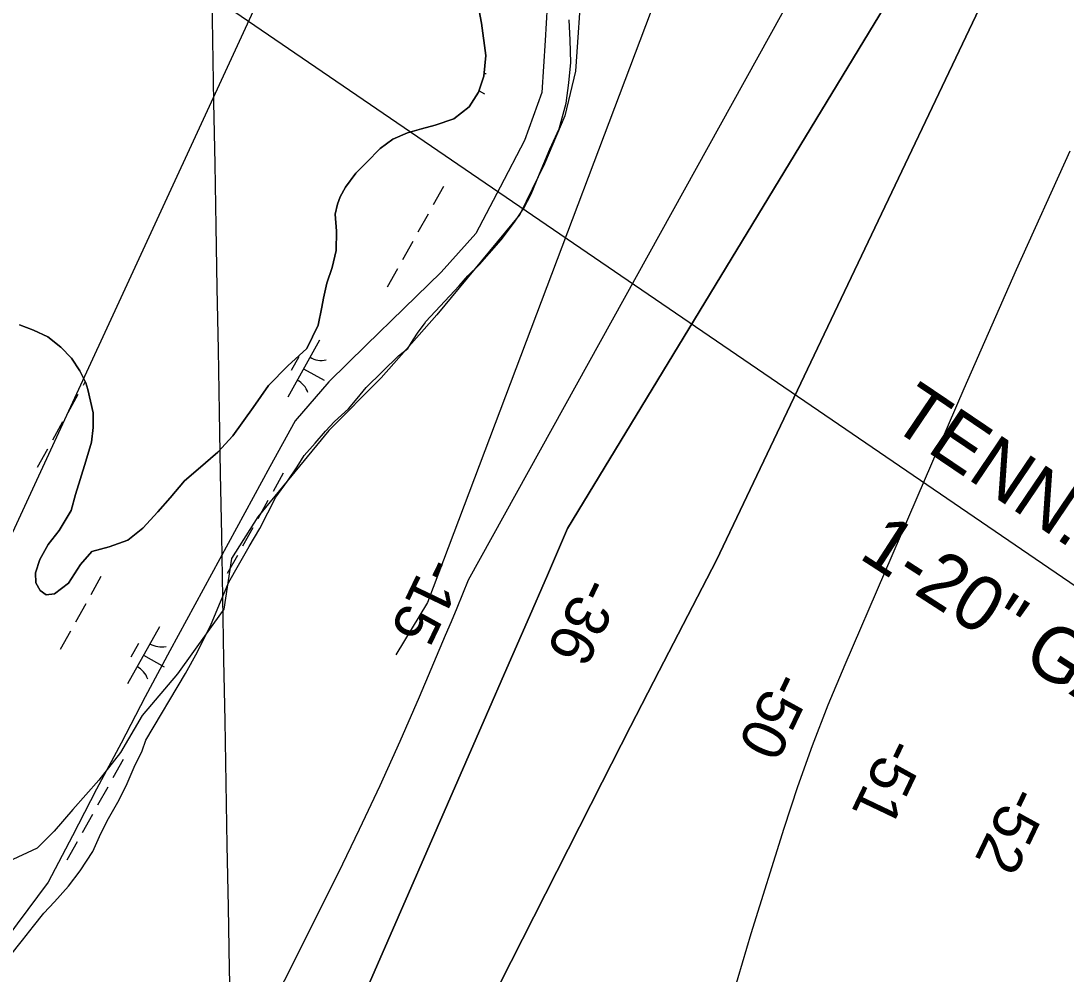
# Model space of a CAD drawing. Extents: x 3923531 to 3943530, y 207391 to 229799.
# Drawn here: x 3935451 to 3936249, y 220366 to 221095 of the extents above; entities that cross this region are included whole.
import ezdxf

# ---------------------------------------------------------------- set-up
doc = ezdxf.new("R2010")
doc.units = 0
for name, color, linetype in [('V-GRID-MAJR', 7, 'Continuous'), ('V-RIVR-EDGE', 7, 'Continuous'), ('V-RIVR-RANG', 7, 'Continuous'), ('V-RRAP-FSHR', 7, 'Continuous'), ('V-TOPO-DPTH', 7, 'Continuous'), ('V-TOPO-MAJR', 7, 'Continuous'), ('V-TOPO-MINR', 7, 'Continuous'), ('V-TOPO-SHOR', 7, 'Continuous'), ('V-UTIL-IDEN', 7, 'Continuous'), ('V-UTIL-LINE', 7, 'Continuous'), ('V-WETL-SWMP', 7, 'Continuous')]:
    doc.layers.add(name, color=color, linetype=linetype)

msp = doc.modelspace()

# ---------------------------------------------------------------- linework, layer by layer
at = {"layer": 'V-GRID-MAJR'}
msp.add_spline([(3935779.93, 210874.81), (3935760.83, 211942.59), (3935652.4, 218002.59), (3935543.98, 224062.57), (3935501.82, 226418.85)], degree=3, dxfattribs=at)
at = {"layer": 'V-RIVR-EDGE'}
msp.add_lwpolyline([(3935879.19, 221126.95), (3935874.48, 221056.23), (3935866.23, 221022.05), (3935850.9, 220985.51), (3935832.04, 220946.61), (3935768.39, 220869.99), (3935725.96, 220821.67), (3935685.88, 220781.59), (3935631.66, 220715.58), (3935611.62, 220683.76), (3935605.73, 220644.86), (3935570.37, 220595.35), (3935543.26, 220563.53), (3935526.76, 220535.24), (3935510.25, 220514.02), (3935490.22, 220491.63), (3935476.07, 220475.12), (3935463.1, 220462.16), (3935440.71, 220451.55), (3935420.67, 220418.55), (3935402.99, 220376.11), (3935397.1, 220347.82)], dxfattribs=at)
at = {"layer": 'V-RRAP-FSHR'}
msp.add_lwpolyline([(3935853.59, 221119.76), (3935851.18, 221079.84), (3935848.78, 221039.91), (3935835.56, 221003.4), (3935816.91, 220967.62), (3935798.25, 220932.24), (3935771.84, 220902.65), (3935743.22, 220874.7), (3935714.61, 220846.74), (3935686, 220818.79), (3935660.36, 220788.84), (3935640.93, 220753.7), (3935621.83, 220718.55), (3935602.72, 220683.41), (3935583.62, 220648.27), (3935564.51, 220613.13), (3935545.56, 220577.9), (3935527.34, 220542.45), (3935508.51, 220507.3), (3935489.98, 220471.55), (3935471.45, 220436.1), (3935447.8, 220404.36), (3935424.14, 220372.27), (3935404.43, 220337.15)], dxfattribs=at)
at = {"layer": 'V-TOPO-DPTH'}
for points in [[(3936215.49, 221431.86), (3935792.56, 220666.96), (3935788.22, 220656.35), (3935783.85, 220645.76), (3935779.43, 220635.19), (3935774.98, 220624.63), (3935755.03, 220577.54), (3935740.26, 220543.6), (3935725.06, 220509.85), (3935709.23, 220476.39), (3935692.98, 220443.13), (3935569.48, 220196.46), (3935540.58, 220139.25), (3935511.41, 220082.19), (3935481.82, 220025.34), (3935451.96, 219968.63), (3935421.78, 219912.09), (3935391.44, 219855.63)], [(3936291.23, 221331.48), (3935982.21, 220682.3), (3935960.23, 220639.98), (3935938.35, 220597.61), (3935916.61, 220555.17), (3935894.96, 220512.68), (3935695.15, 220118.89), (3935679.69, 220088.59), (3935664.13, 220058.35), (3935648.42, 220028.18), (3935632.61, 219998.06), (3935609.7, 219954.67), (3935605.24, 219946.3), (3935600.74, 219937.96), (3935596.17, 219929.65), (3935591.57, 219921.37), (3935451.61, 219672.01)], [(3935451.61, 219672.01), (3935591.57, 219921.37), (3935596.17, 219929.65), (3935600.74, 219937.96), (3935605.24, 219946.3), (3935609.7, 219954.67), (3935632.61, 219998.06), (3935648.42, 220028.18), (3935664.13, 220058.35), (3935679.69, 220088.59), (3935695.15, 220118.89), (3935894.96, 220512.68), (3935916.61, 220555.17), (3935938.35, 220597.61), (3935960.23, 220639.98), (3935982.21, 220682.3), (3936291.23, 221331.48)], [(3935279.42, 219531.78), (3935501.82, 219920.93), (3935516.95, 219947.86), (3935531.82, 219974.93), (3935546.3, 220002.21), (3935560.52, 220029.62), (3935591.1, 220089.63), (3935619.88, 220147.41), (3935647.97, 220205.52), (3935675.02, 220264.12), (3935701.36, 220323.05), (3935806.56, 220564.15), (3935822.07, 220599.72), (3935837.55, 220635.29), (3935853, 220670.88), (3935868.43, 220706.48), (3936232.07, 221305.79)], [(3935279.42, 219531.78), (3935501.82, 219920.93), (3935516.95, 219947.86), (3935531.82, 219974.93), (3935546.3, 220002.21), (3935560.52, 220029.62), (3935591.1, 220089.63), (3935619.88, 220147.41), (3935647.97, 220205.52), (3935675.02, 220264.12), (3935701.36, 220323.05), (3935806.56, 220564.15), (3935822.07, 220599.72), (3935837.55, 220635.29), (3935853, 220670.88), (3935868.43, 220706.48), (3936232.07, 221305.79)]]:
    msp.add_lwpolyline(points, dxfattribs=at)
at = {"layer": 'V-TOPO-MAJR'}
msp.add_lwpolyline([(3936252.14, 220995.05), (3936211.34, 220904.39), (3936171.32, 220813.37), (3936080.18, 220602.31), (3936067.43, 220571.46), (3936055.33, 220540.37), (3936044.21, 220508.91), (3936033.74, 220477.22), (3936008.49, 220396.55), (3936001.76, 220374.23), (3935995.34, 220351.83), (3935989.39, 220329.3), (3935983.74, 220306.69), (3935978.25, 220284.03), (3935972.65, 220261.4), (3935966.89, 220238.81), (3935961.01, 220216.24), (3935951.66, 220180.85), (3935940.7, 220140.71), (3935929.29, 220100.7), (3935917.22, 220060.89), (3935904.71, 220021.21), (3935843.41, 219832.29)], dxfattribs=at)
at = {"layer": 'V-TOPO-MINR'}
for points in [[(3936528.75, 222374.13), (3936417.66, 222129.09), (3936366.69, 222020.1), (3936314.03, 221911.96), (3936258.82, 221805.09), (3936201.92, 221699.07), (3936118.61, 221548.14), (3936102.54, 221518.01), (3936087.05, 221487.59), (3936072.45, 221456.74), (3936058.43, 221425.6), (3936055.62, 221419.11), (3936040.88, 221384.4), (3936026.48, 221349.57), (3936012.58, 221314.53), (3935999.01, 221279.35), (3935761.43, 220650.11), (3935737.16, 220609.89)], [(3936215.49, 221431.86), (3935792.56, 220666.96), (3935788.22, 220656.35), (3935783.85, 220645.76), (3935779.43, 220635.19), (3935774.98, 220624.63), (3935755.03, 220577.54), (3935740.26, 220543.6), (3935725.06, 220509.85), (3935709.23, 220476.39), (3935692.98, 220443.13), (3935569.48, 220196.46), (3935540.58, 220139.25), (3935511.41, 220082.19), (3935481.82, 220025.34), (3935451.96, 219968.63), (3935421.78, 219912.09), (3935391.44, 219855.63)], [(3936291.23, 221331.48), (3935982.21, 220682.3), (3935960.23, 220639.98), (3935938.35, 220597.61), (3935916.61, 220555.17), (3935894.96, 220512.68), (3935695.15, 220118.89), (3935679.69, 220088.59), (3935664.13, 220058.35), (3935648.42, 220028.18), (3935632.61, 219998.06), (3935609.7, 219954.67), (3935605.24, 219946.3), (3935600.74, 219937.96), (3935596.17, 219929.65), (3935591.57, 219921.37), (3935451.61, 219672.01)], [(3936232.07, 221305.79), (3935868.43, 220706.48), (3935853, 220670.88), (3935837.55, 220635.29), (3935822.07, 220599.72), (3935806.56, 220564.15), (3935701.36, 220323.05), (3935675.02, 220264.12), (3935647.97, 220205.52), (3935619.88, 220147.41), (3935591.1, 220089.63), (3935560.52, 220029.62), (3935546.3, 220002.21), (3935531.82, 219974.93), (3935516.95, 219947.86), (3935501.82, 219920.93), (3935279.42, 219531.78)]]:
    msp.add_lwpolyline(points, dxfattribs=at)
at = {"layer": 'V-TOPO-SHOR'}
for points in [[(3935471.12, 220853.15), (3935481.06, 220845.24), (3935489.42, 220836.93), (3935495.79, 220827.03), (3935500.18, 220817.91), (3935501.79, 220812.76), (3935505.8, 220794.91), (3935505.83, 220783.8), (3935504.67, 220772.69), (3935500.34, 220757.99), (3935496.02, 220744.09), (3935492.48, 220732.57), (3935488.94, 220720.26), (3935479.85, 220705.16), (3935471.55, 220694.42), (3935465.23, 220682.9), (3935461.68, 220672.57), (3935462.1, 220665.03), (3935465.29, 220659.09), (3935470.06, 220655.93), (3935476.41, 220656.74), (3935487.1, 220664.7), (3935496.19, 220679.01), (3935504.89, 220688.95), (3935517.98, 220692.56), (3935532.25, 220697.76), (3935543.73, 220706.92), (3935555.21, 220719.25), (3935564.7, 220729.99), (3935575.78, 220743.11), (3935586.07, 220751.87), (3935601.12, 220765.01), (3935612.59, 220777.34), (3935628.01, 220799.21), (3935639.87, 220815.9), (3935654.51, 220831.02), (3935669.16, 220844.16), (3935677.84, 220862.04), (3935680.58, 220875.93), (3935681.76, 220882.68), (3935684.5, 220894.2), (3935688.44, 220906.12), (3935691.58, 220919.22), (3935691.94, 220933.9), (3935690.71, 220947), (3935692.68, 220954.54), (3935694.65, 220960.1), (3935698.59, 220967.65), (3935706.5, 220978.39), (3935714.81, 220986.34), (3935725.1, 220997.09), (3935735, 221004.26), (3935746.1, 221009.05), (3935756.81, 221012.25), (3935767.12, 221015.06), (3935781.39, 221019.86), (3935793.27, 221029.02), (3935800.38, 221040.15), (3935804.32, 221052.46), (3935805.86, 221068.34), (3935802.62, 221092.93), (3935799.4, 221110.78)], [(3935449.67, 220862.22), (3935460.39, 220858.28), (3935471.12, 220853.15)]]:
    msp.add_lwpolyline(points, dxfattribs=at)
at = {"layer": 'V-UTIL-LINE'}
msp.add_line((3933790.65, 222348.75), (3937515.29, 219801.86), dxfattribs=at)
msp.add_lwpolyline([(3936103.37, 223826.38), (3936685.98, 223703.71), (3936312.74, 222585.97), (3935348.71, 220497.13)], dxfattribs=at)
at = {"layer": 'V-WETL-SWMP'}
for p, q in [((3935799.4, 221110.78), (3935802.62, 221092.93)), ((3935802.62, 221092.93), (3935805.86, 221068.34)), ((3935870.48, 221080.04), (3935869.64, 221095.54)), ((3935870.92, 221062.96), (3935870.48, 221080.04)), ((3935805.86, 221068.34), (3935804.32, 221052.46)), ((3935869.37, 221047.45), (3935870.92, 221062.96)), ((3935804.32, 221052.46), (3935800.38, 221040.15)), ((3935800.76, 221041.32), (3935804.83, 221039.05)), ((3935867.42, 221031.95), (3935869.37, 221047.45)), ((3935800.38, 221040.15), (3935793.27, 221029.02)), ((3935793.27, 221029.02), (3935781.39, 221019.86)), ((3935861.91, 221012.07), (3935867.42, 221031.95)), ((3935781.39, 221019.86), (3935767.12, 221015.06)), ((3935746.1, 221009.05), (3935735, 221004.26)), ((3935756.81, 221012.25), (3935746.1, 221009.05)), ((3935767.12, 221015.06), (3935756.81, 221012.25)), ((3935854.8, 220996.55), (3935861.91, 221012.07)), ((3935735, 221004.26), (3935725.1, 220997.09)), ((3935725.1, 220997.09), (3935714.81, 220986.35)), ((3935846.91, 220977.85), (3935854.8, 220996.55)), ((3935714.81, 220986.35), (3935706.5, 220978.39)), ((3935706.5, 220978.39), (3935698.59, 220967.65)), ((3935840.59, 220962.34), (3935846.91, 220977.85)), ((3935698.59, 220967.65), (3935694.64, 220960.1)), ((3935773.56, 220967.98), (3935765.76, 220954.01)), ((3935835.06, 220951.59), (3935840.59, 220962.34)), ((3935692.68, 220954.54), (3935690.71, 220947)), ((3935694.64, 220960.1), (3935692.68, 220954.54)), ((3935690.71, 220947), (3935691.94, 220933.9)), ((3935761.86, 220947.02), (3935754.05, 220933.06)), ((3935827.93, 220940.85), (3935835.06, 220951.59)), ((3935817.64, 220927.31), (3935827.93, 220940.85)), ((3935691.94, 220933.9), (3935691.58, 220919.22)), ((3935750.15, 220926.07), (3935742.35, 220912.1)), ((3935808.52, 220916.95), (3935817.64, 220927.31)), ((3935691.58, 220919.22), (3935688.44, 220906.12)), ((3935801.39, 220908.59), (3935808.52, 220916.95)), ((3935688.44, 220906.12), (3935684.5, 220894.2)), ((3935738.45, 220905.12), (3935730.64, 220891.15)), ((3935792.28, 220899.82), (3935801.39, 220908.59)), ((3935785.54, 220892.25), (3935792.28, 220899.82)), ((3935684.5, 220894.2), (3935681.76, 220882.69)), ((3935760.17, 220864.8), (3935785.54, 220892.25)), ((3935681.76, 220882.69), (3935680.58, 220875.94)), ((3935680.58, 220875.94), (3935677.84, 220862.04)), ((3935758.97, 220862.98), (3935760.17, 220864.8)), ((3935460.39, 220858.28), (3935449.67, 220862.22)), ((3935471.12, 220853.15), (3935460.39, 220858.28)), ((3935677.84, 220862.04), (3935669.16, 220844.16)), ((3935750.47, 220850.91), (3935754.12, 220856.65)), ((3935754.12, 220856.65), (3935758.97, 220862.98)), ((3935481.06, 220845.24), (3935471.12, 220853.15)), ((3935678.91, 220850.57), (3935654.53, 220806.92)), ((3935746.42, 220844.18), (3935750.47, 220850.91)), ((3935489.42, 220836.93), (3935481.06, 220845.24)), ((3935669.16, 220844.16), (3935654.51, 220831.02)), ((3935739.18, 220838.67), (3935746.42, 220844.18)), ((3935495.79, 220827.03), (3935489.42, 220836.93)), ((3935662.91, 220837.75), (3935657.06, 220827.27)), ((3935714.41, 220814.41), (3935739.18, 220838.67)), ((3935500.18, 220817.91), (3935495.79, 220827.03)), ((3935654.51, 220831.02), (3935639.87, 220815.91)), ((3935666.72, 220828.74), (3935682.43, 220819.97)), ((3935499.73, 220818.86), (3935498.15, 220816.05)), ((3935501.78, 220812.76), (3935500.18, 220817.91)), ((3935494.25, 220809.06), (3935486.45, 220795.1)), ((3935505.8, 220794.91), (3935501.78, 220812.76)), ((3935639.87, 220815.91), (3935628.01, 220799.21)), ((3935707.55, 220805.9), (3935714.41, 220814.41)), ((3935701.09, 220798.2), (3935707.55, 220805.9)), ((3935505.83, 220783.8), (3935505.8, 220794.91)), ((3935628.01, 220799.21), (3935612.59, 220777.34)), ((3935690.42, 220788.34), (3935701.09, 220798.2)), ((3935482.55, 220788.11), (3935474.74, 220774.14)), ((3935683.37, 220781.04), (3935690.42, 220788.34)), ((3935504.67, 220772.69), (3935505.83, 220783.8)), ((3935612.59, 220777.34), (3935601.12, 220765.01)), ((3935675.5, 220771.95), (3935683.37, 220781.04)), ((3935500.34, 220757.99), (3935504.67, 220772.69)), ((3935667.03, 220762.27), (3935675.5, 220771.95)), ((3935470.84, 220767.16), (3935463.04, 220753.19)), ((3935601.12, 220765.01), (3935586.07, 220751.87)), ((3935661.75, 220753.75), (3935667.03, 220762.27)), ((3935496.01, 220744.09), (3935500.34, 220757.99)), ((3935654.27, 220742.86), (3935661.75, 220753.75)), ((3935586.07, 220751.87), (3935575.78, 220743.11)), ((3935651.17, 220748.89), (3935643.37, 220734.92)), ((3935492.47, 220732.57), (3935496.01, 220744.09)), ((3935575.78, 220743.11), (3935564.7, 220729.99)), ((3935645.37, 220730.6), (3935654.27, 220742.86)), ((3935488.94, 220720.26), (3935492.47, 220732.57)), ((3935564.7, 220729.99), (3935555.21, 220719.25)), ((3935633.16, 220706.6), (3935645.37, 220730.6)), ((3935639.46, 220727.94), (3935631.66, 220713.97)), ((3935479.85, 220705.16), (3935488.94, 220720.26)), ((3935555.21, 220719.25), (3935543.73, 220706.92)), ((3935471.54, 220694.42), (3935479.85, 220705.16)), ((3935543.73, 220706.92), (3935532.25, 220697.76)), ((3935627.76, 220706.99), (3935619.96, 220693.02)), ((3935625.04, 220692.73), (3935633.16, 220706.6)), ((3935532.25, 220697.76), (3935517.98, 220692.56)), ((3935465.23, 220682.9), (3935471.54, 220694.42)), ((3935504.89, 220688.96), (3935496.19, 220679.01)), ((3935517.98, 220692.56), (3935504.89, 220688.96)), ((3935616.92, 220678.46), (3935625.04, 220692.73)), ((3935461.68, 220672.57), (3935465.23, 220682.9)), ((3935616.05, 220686.03), (3935608.25, 220672.07)), ((3935496.19, 220679.01), (3935487.1, 220664.7)), ((3935609.61, 220665.58), (3935616.92, 220678.46)), ((3935462.1, 220665.03), (3935461.68, 220672.57)), ((3935465.29, 220659.09), (3935462.1, 220665.03)), ((3935511.84, 220669.85), (3935504.04, 220655.88)), ((3935603.07, 220650.5), (3935609.61, 220665.58)), ((3935470.06, 220655.93), (3935465.29, 220659.09)), ((3935487.1, 220664.7), (3935476.41, 220656.74)), ((3935476.41, 220656.74), (3935470.06, 220655.93)), ((3935500.14, 220648.9), (3935492.33, 220634.93)), ((3935596.12, 220633.43), (3935603.07, 220650.5)), ((3935585.53, 220612.21), (3935596.12, 220633.43)), ((3935488.43, 220627.95), (3935480.63, 220613.98)), ((3935556.52, 220631.49), (3935532.13, 220587.84)), ((3935540.52, 220618.66), (3935534.66, 220608.19)), ((3935544.33, 220609.66), (3935560.04, 220600.88)), ((3935576.39, 220595.76), (3935585.53, 220612.21)), ((3935546.16, 220544.64), (3935576.39, 220595.76)), ((3935543.29, 220536.49), (3935546.16, 220544.64)), ((3935528.78, 220529.81), (3935520.97, 220515.84)), ((3935537.18, 220524), (3935543.29, 220536.49)), ((3935531.86, 220511.49), (3935537.18, 220524)), ((3935517.07, 220508.85), (3935509.27, 220494.89)), ((3935525.76, 220499.2), (3935531.86, 220511.49)), ((3935516.62, 220483.15), (3935525.76, 220499.2)), ((3935505.37, 220487.9), (3935497.56, 220473.93)), ((3935510.71, 220471.05), (3935516.62, 220483.15)), ((3935493.66, 220466.95), (3935485.86, 220452.98)), ((3935505.61, 220459.54), (3935510.71, 220471.05)), ((3935495.89, 220444.69), (3935505.61, 220459.54)), ((3935487, 220433.02), (3935495.89, 220444.69)), ((3935476.31, 220420.97), (3935487, 220433.02)), ((3935468.04, 220412.48), (3935476.31, 220420.97)), ((3935460.17, 220402.4), (3935468.04, 220412.48)), ((3935451.88, 220391.72), (3935460.17, 220402.4)), ((3935441.99, 220379.26), (3935451.88, 220391.72))]:
    msp.add_line(p, q, dxfattribs=at)
for centre, start, end in [((3935802.79, 221071.83), 275.55922, 281.58174), ((3935680.4, 220852.74), 240.03808, 281.58174), ((3935653.45, 220804.52), 20.03808, 61.58174), ((3935558, 220633.66), 240.03808, 281.58174), ((3935531.06, 220585.43), 20.03808, 61.58174)]:
    msp.add_arc(centre, 17.62, start, end, dxfattribs=at)

# ---------------------------------------------------------------- texts
at = {"layer": 'V-RIVR-RANG'}
for s, rotation, p in [('-15', 244.34833, (3935760.67, 220687.2)), ('-36', 244.48914, (3935880.04, 220671.73)), ('-50', 244.48914, (3936026.1, 220599.57)), ('-51', 244.48914, (3936112.86, 220548.74)), ('-52', 244.48914, (3936207.01, 220511.77))]:
    msp.add_text(s, height=33.5, rotation=rotation, dxfattribs=at).set_placement(p)
at = {"layer": 'V-UTIL-IDEN'}
for s, rotation, p in [('TENN. GAS TRANS CO.', 325.95899, (3936113.45, 220785.31)), ('1-20" GAS PIPELINE', 327.12689, (3936089.97, 220684.53))]:
    msp.add_text(s, height=41.9999, rotation=rotation, dxfattribs=at).set_placement(p)

doc.saveas('drawing.dxf')
